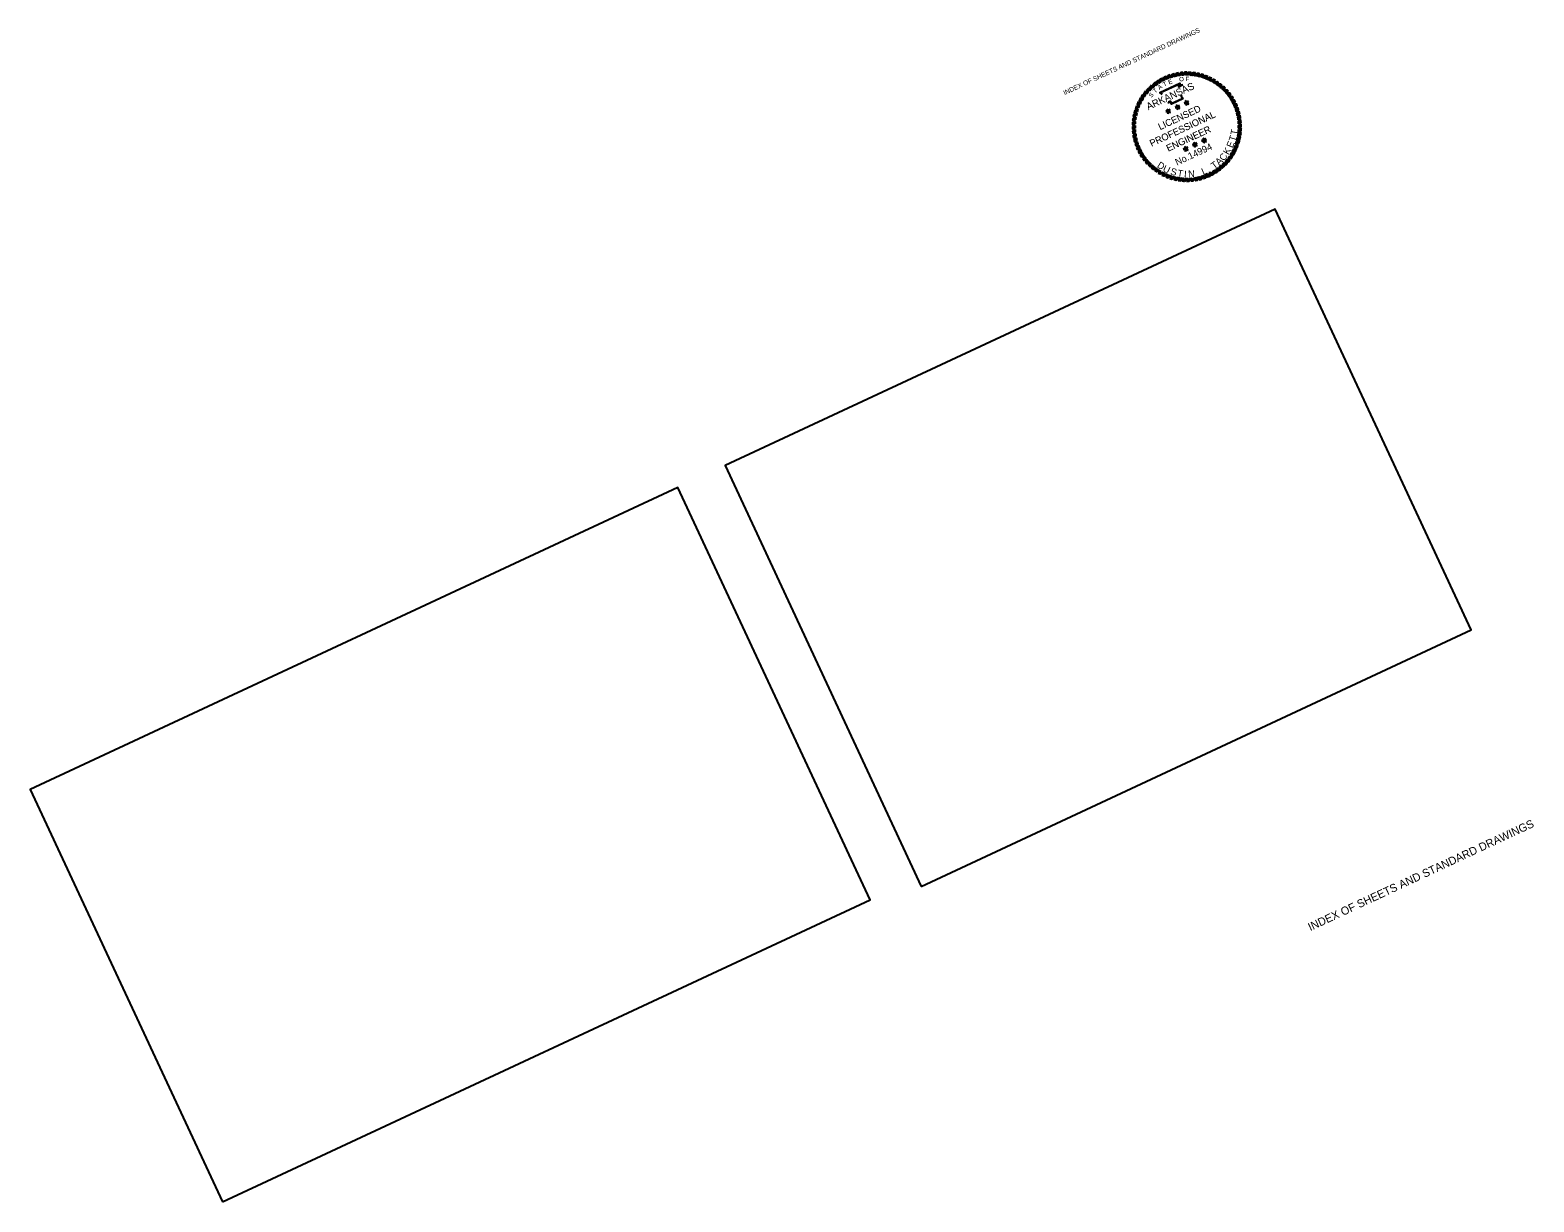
# Model space of a CAD drawing. Extents: x -22487163 to -22480035, y -237910427 to -237906052.
# Drawn here: x -22487163 to -22483810, y -237910427 to -237907814 of the extents above; entities that cross this region are included whole.
import ezdxf

# ---------------------------------------------------------------- set-up
doc = ezdxf.new("R2010")
doc.units = 0
for name, color, linetype in [('53', 7, 'Continuous'), ('54', 7, 'Continuous'), ('Default', 7, 'Continuous')]:
    doc.layers.add(name, color=color, linetype=linetype)

# ---------------------------------------------------------------- blocks, each defined once
blk = doc.blocks.new('STAR')
at = {"layer": 'Default'}
for p, q in [((0.059, 0.019), (-0.059, 0.019)), ((-0.059, 0.019), (0.036, -0.05)), ((0, 0.062), (-0.037, -0.05)), ((-0.036, -0.05), (0.059, 0.019)), ((-0.008, 0), (0.009, 0)), ((0.036, -0.05), (0, 0.062)), ((0, 0.006), (0, -0.008))]:
    blk.add_line(p, q, dxfattribs=at)
blk = doc.blocks.new('RP')
at = {"layer": 'Default'}
for p, q in [((-0.078, 1.266), (0.003, 1.33)), ((-0.058, 1.267), (0.022, 1.33)), ((-0.038, 1.267), (0.04, 1.329)), ((-0.018, 1.268), (0.059, 1.329))]:
    blk.add_line(p, q, dxfattribs=at)
for radius, start, end in [(1.268, 90.7933, 93.5307), (1.33, 87.4562, 89.8699)]:
    blk.add_arc((0, 0), radius, start, end, dxfattribs=at)

msp = doc.modelspace()

# ---------------------------------------------------------------- linework, layer by layer
at = {"layer": '54'}
for points in [[(-22485175.9, -237909723.4), (-22483949.6, -237909151.5), (-22484387.2, -237908213.1), (-22485613.5, -237908784.9)], [(-22486734.3, -237910427), (-22485289.7, -237909753.4), (-22485718.4, -237908833.9), (-22487163, -237909507.5)]]:
    msp.add_lwpolyline(points, close=True, dxfattribs=at)
at = {"layer": 'Default'}
for points in [[(-22484638.7, -237907957.7), (-22484643.9, -237907953.3), (-22484599.4, -237907932.6), (-22484601, -237907939), (-22484598, -237907937.5), (-22484595.5, -237907936.3), (-22484592.8, -237907935.4)], [(-22484638.6, -237907957.6), (-22484643.8, -237907953.2), (-22484599.3, -237907932.6), (-22484600.8, -237907939), (-22484597.8, -237907937.6), (-22484595.3, -237907936.4), (-22484592.7, -237907935.5)], [(-22484638.2, -237907957.1), (-22484642.4, -237907953.5), (-22484600.6, -237907934), (-22484602.1, -237907940.4), (-22484597.6, -237907938.2), (-22484595.2, -237907937), (-22484592.6, -237907936.2)], [(-22484638.1, -237907957), (-22484642.3, -237907953.4), (-22484600.4, -237907934), (-22484602, -237907940.4), (-22484597.5, -237907938.3), (-22484595, -237907937.1), (-22484592.4, -237907936.2)], [(-22484595.1, -237907960.1), (-22484595.5, -237907961.1), (-22484595.4, -237907962.2), (-22484594.6, -237907964.6), (-22484593.1, -237907967.7), (-22484618, -237907979.1), (-22484619.9, -237907975), (-22484620.3, -237907974.1), (-22484621.5, -237907974.2), (-22484625, -237907975.9), (-22484626.1, -237907975.2)], [(-22484595.1, -237907960.1), (-22484595.6, -237907961), (-22484595.4, -237907962.1), (-22484594.6, -237907964.5), (-22484593.2, -237907967.6), (-22484618, -237907979.1), (-22484619.9, -237907975), (-22484620.4, -237907974.1), (-22484621.5, -237907974.2), (-22484625, -237907975.9), (-22484626.1, -237907975.2)], [(-22484595.8, -237907959.7), (-22484596.4, -237907960.9), (-22484596.2, -237907962.3), (-22484595.3, -237907964.8), (-22484594.2, -237907967.2), (-22484617.6, -237907978.1), (-22484619.2, -237907974.7), (-22484619.9, -237907973.2), (-22484621.7, -237907973.5), (-22484625, -237907975), (-22484625.7, -237907974.6)], [(-22484595.8, -237907959.8), (-22484596.4, -237907961), (-22484596.1, -237907962.3), (-22484595.3, -237907964.9), (-22484594.2, -237907967.3), (-22484617.6, -237907978.1), (-22484619.2, -237907974.7), (-22484619.9, -237907973.2), (-22484621.7, -237907973.5), (-22484625, -237907975), (-22484625.7, -237907974.5)]]:
    msp.add_lwpolyline(points, dxfattribs=at)

# ---------------------------------------------------------------- block references
for name, p, xscale, yscale, rotation in [('RP', (-22484583.8, -237908029.4), 91.17655343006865, 91.17655343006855, 34.000000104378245), ('RP', (-22484583.9, -237908029.6), 91.17655343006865, 91.17655343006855, 33.804199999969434), ('RP', (-22484583.8, -237908029.4), 91.17655343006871, 91.17655343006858, 29.500000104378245), ('RP', (-22484583.9, -237908029.6), 91.17655343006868, 91.17655343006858, 29.30419999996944), ('RP', (-22484583.8, -237908029.4), 91.17655343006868, 91.17655343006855, 25.00000010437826), ('RP', (-22484583.9, -237908029.6), 91.17655343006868, 91.17655343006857, 24.804199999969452), ('RP', (-22484583.8, -237908029.4), 91.1765534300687, 91.17655343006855, 20.50000010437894), ('RP', (-22484583.9, -237908029.6), 91.17655343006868, 91.17655343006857, 20.304199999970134), ('RP', (-22484583.8, -237908029.4), 91.1765534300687, 91.17655343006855, 16.00000010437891), ('RP', (-22484583.9, -237908029.6), 91.1765534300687, 91.17655343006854, 15.804199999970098), ('RP', (-22484583.8, -237908029.4), 91.17655343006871, 91.17655343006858, 11.500000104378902), ('RP', (-22484583.9, -237908029.6), 91.17655343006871, 91.1765534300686, 11.304199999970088), ('RP', (-22484583.8, -237908029.4), 91.17655343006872, 91.17655343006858, 7.000000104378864), ('RP', (-22484583.9, -237908029.6), 91.1765534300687, 91.17655343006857, 6.804199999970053), ('RP', (-22484583.8, -237908029.4), 91.17655343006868, 91.17655343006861, 2.500000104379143), ('RP', (-22484583.9, -237908029.6), 91.17655343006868, 91.17655343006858, 2.30419999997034), ('RP', (-22484583.8, -237908029.4), 91.17655343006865, 91.17655343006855, -1.999999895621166), ('RP', (-22484583.9, -237908029.6), 91.17655343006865, 91.17655343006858, -2.19580000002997), ('RP', (-22484583.8, -237908029.4), 91.1765534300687, 91.17655343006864, -6.499999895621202), ('RP', (-22484583.9, -237908029.6), 91.17655343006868, 91.17655343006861, -6.695800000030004), ('RP', (-22484583.8, -237908029.4), 91.17655343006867, 91.17655343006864, -10.99999989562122), ('RP', (-22484583.9, -237908029.6), 91.17655343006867, 91.17655343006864, -11.195800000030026), ('RP', (-22484583.8, -237908029.4), 91.17655343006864, 91.1765534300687, -15.499999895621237), ('RP', (-22484583.9, -237908029.6), 91.17655343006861, 91.17655343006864, -15.695800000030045), ('RP', (-22484583.8, -237908029.4), 91.17655343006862, 91.17655343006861, -19.99999989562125), ('RP', (-22484583.9, -237908029.6), 91.17655343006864, 91.1765534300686, -20.195800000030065), ('RP', (-22484583.8, -237908029.4), 91.1765534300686, 91.17655343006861, -24.499999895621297), ('RP', (-22484583.9, -237908029.6), 91.1765534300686, 91.17655343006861, -24.695800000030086), ('RP', (-22484583.8, -237908029.4), 91.17655343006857, 91.17655343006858, -28.999999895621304), ('RP', (-22484583.9, -237908029.6), 91.17655343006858, 91.17655343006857, -29.19580000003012), ('RP', (-22484583.8, -237908029.4), 91.17655343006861, 91.17655343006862, -33.49999989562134), ('RP', (-22484583.9, -237908029.6), 91.17655343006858, 91.17655343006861, -33.69580000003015), ('RP', (-22484583.9, -237908029.6), 91.17655343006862, 91.17655343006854, 56.304199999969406), ('RP', (-22484583.8, -237908029.4), 91.17655343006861, 91.17655343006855, 56.500000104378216), ('RP', (-22484583.8, -237908029.4), 91.17655343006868, 91.17655343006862, 52.000000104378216), ('RP', (-22484583.9, -237908029.6), 91.17655343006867, 91.17655343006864, 51.8041999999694), ('RP', (-22484583.8, -237908029.4), 91.17655343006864, 91.1765534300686, 47.500000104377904), ('RP', (-22484583.9, -237908029.6), 91.17655343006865, 91.17655343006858, 47.30419999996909), ('RP', (-22484583.8, -237908029.4), 91.17655343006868, 91.17655343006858, 43.00000010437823), ('RP', (-22484583.9, -237908029.6), 91.17655343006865, 91.17655343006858, 42.80419999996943), ('RP', (-22484583.8, -237908029.4), 91.17655343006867, 91.17655343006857, 38.50000010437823), ('RP', (-22484583.9, -237908029.6), 91.17655343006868, 91.17655343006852, 38.304199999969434), ('RP', (-22484583.8, -237908029.4), 91.17655343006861, 91.17655343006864, -37.99999989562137), ('RP', (-22484583.9, -237908029.6), 91.17655343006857, 91.17655343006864, -38.19580000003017), ('RP', (-22484583.8, -237908029.4), 91.1765534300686, 91.17655343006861, -42.49999989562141), ('RP', (-22484583.9, -237908029.6), 91.1765534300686, 91.17655343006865, -42.69580000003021), ('RP', (-22484583.8, -237908029.4), 91.17655343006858, 91.17655343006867, -46.99999989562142), ('RP', (-22484583.9, -237908029.6), 91.17655343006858, 91.17655343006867, -47.19580000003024), ('RP', (-22484583.8, -237908029.4), 91.17655343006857, 91.1765534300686, -51.49999989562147), ('RP', (-22484583.9, -237908029.6), 91.1765534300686, 91.17655343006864, -51.69580000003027), ('RP', (-22484583.8, -237908029.4), 91.17655343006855, 91.17655343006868, -55.999999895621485), ('RP', (-22484583.9, -237908029.6), 91.17655343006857, 91.17655343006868, -56.195800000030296), ('RP', (-22484583.9, -237908029.6), 91.17655343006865, 91.17655343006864, 74.30419999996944), ('RP', (-22484583.8, -237908029.4), 91.17655343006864, 91.17655343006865, 74.50000010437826), ('RP', (-22484583.9, -237908029.6), 91.17655343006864, 91.17655343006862, 69.80419999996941), ('RP', (-22484583.8, -237908029.4), 91.17655343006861, 91.17655343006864, 70.0000001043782), ('RP', (-22484583.9, -237908029.6), 91.17655343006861, 91.1765534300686, 65.30419999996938), ('RP', (-22484583.8, -237908029.4), 91.17655343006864, 91.17655343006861, 65.50000010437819), ('RP', (-22484583.9, -237908029.6), 91.17655343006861, 91.17655343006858, 60.80419999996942), ('RP', (-22484583.8, -237908029.4), 91.17655343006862, 91.17655343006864, 61.000000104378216), ('STAR', (-22484625, -237907995.2), 91.17655343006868, 91.17655343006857, 24.804199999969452), ('STAR', (-22484625, -237907995.2), 91.17655343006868, 91.17655343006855, 25.00000010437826), ('STAR', (-22484604.5, -237907985.7), 91.17655343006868, 91.17655343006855, 25.00000010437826), ('STAR', (-22484604.5, -237907985.8), 91.17655343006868, 91.17655343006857, 24.804199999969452), ('STAR', (-22484584.1, -237907976.2), 91.17655343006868, 91.17655343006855, 25.00000010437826), ('STAR', (-22484584.1, -237907976.3), 91.17655343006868, 91.17655343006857, 24.804199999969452), ('RP', (-22484583.8, -237908029.4), 91.17655343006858, 91.17655343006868, -60.49999989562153), ('RP', (-22484583.9, -237908029.6), 91.17655343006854, 91.17655343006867, -60.69580000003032), ('RP', (-22484583.8, -237908029.4), 91.17655343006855, 91.1765534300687, -64.99999989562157), ('RP', (-22484583.9, -237908029.6), 91.17655343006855, 91.1765534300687, -65.19580000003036), ('RP', (-22484583.8, -237908029.4), 91.1765534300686, 91.17655343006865, -69.49999989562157), ('RP', (-22484583.9, -237908029.6), 91.17655343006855, 91.17655343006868, -69.69580000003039), ('RP', (-22484583.8, -237908029.4), 91.17655343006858, 91.17655343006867, -73.9999998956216), ('RP', (-22484583.9, -237908029.6), 91.17655343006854, 91.17655343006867, -74.19580000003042), ('RP', (-22484583.9, -237908029.6), 91.17655343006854, 91.17655343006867, 87.80419999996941), ('RP', (-22484583.9, -237908029.6), 91.17655343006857, 91.17655343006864, 83.30419999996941), ('RP', (-22484583.8, -237908029.4), 91.1765534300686, 91.17655343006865, 88.00000010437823), ('RP', (-22484583.8, -237908029.4), 91.17655343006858, 91.17655343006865, 83.50000010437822), ('RP', (-22484583.9, -237908029.6), 91.17655343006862, 91.17655343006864, 78.80419999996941), ('RP', (-22484583.8, -237908029.4), 91.17655343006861, 91.17655343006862, 79.00000010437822), ('RP', (-22484583.9, -237908029.6), 91.17655343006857, 91.17655343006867, -78.69580000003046), ('RP', (-22484583.8, -237908029.4), 91.17655343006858, 91.17655343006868, -78.49999989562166), ('RP', (-22484583.9, -237908029.6), 91.17655343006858, 91.17655343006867, -83.19580000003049), ('RP', (-22484583.8, -237908029.4), 91.17655343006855, 91.17655343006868, -82.99999989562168), ('RP', (-22484583.9, -237908029.6), 91.17655343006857, 91.1765534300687, -87.69580000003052), ('RP', (-22484583.8, -237908029.4), 91.17655343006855, 91.17655343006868, -87.49999989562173), ('RP', (-22484583.8, -237908029.4), 91.17655343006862, 91.17655343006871, -91.99999989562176), ('RP', (-22484583.9, -237908029.6), 91.17655343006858, 91.17655343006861, 92.3041999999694), ('RP', (-22484583.8, -237908029.4), 91.1765534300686, 91.17655343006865, 92.50000010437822), ('RP', (-22484583.9, -237908029.6), 91.17655343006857, 91.17655343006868, 96.80419999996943), ('RP', (-22484583.8, -237908029.4), 91.17655343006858, 91.17655343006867, 97.00000010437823), ('RP', (-22484583.9, -237908029.6), 91.17655343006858, 91.17655343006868, 101.30419999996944), ('RP', (-22484583.8, -237908029.4), 91.17655343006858, 91.17655343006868, 101.50000010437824), ('RP', (-22484583.9, -237908029.6), 91.17655343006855, 91.17655343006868, 105.80419999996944), ('RP', (-22484583.8, -237908029.4), 91.17655343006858, 91.17655343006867, 106.00000010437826), ('STAR', (-22484545.3, -237908060.2), 91.17655343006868, 91.17655343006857, 24.804199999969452), ('STAR', (-22484545, -237908060), 91.17655343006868, 91.17655343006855, 25.00000010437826), ('RP', (-22484583.9, -237908029.6), 91.17655343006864, 91.17655343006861, -105.69580000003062), ('RP', (-22484583.8, -237908029.4), 91.17655343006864, 91.17655343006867, -105.49999989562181), ('RP', (-22484583.9, -237908029.6), 91.17655343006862, 91.17655343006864, -101.19580000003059), ('RP', (-22484583.8, -237908029.4), 91.17655343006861, 91.17655343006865, -100.99999989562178), ('RP', (-22484583.9, -237908029.6), 91.17655343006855, 91.17655343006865, -96.69580000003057), ('RP', (-22484583.8, -237908029.4), 91.17655343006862, 91.17655343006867, -96.49999989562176), ('RP', (-22484583.9, -237908029.6), 91.17655343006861, 91.1765534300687, -92.19580000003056), ('RP', (-22484583.9, -237908029.6), 91.17655343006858, 91.17655343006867, 110.30419999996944), ('RP', (-22484583.8, -237908029.4), 91.17655343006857, 91.1765534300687, 110.50000010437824), ('RP', (-22484583.9, -237908029.6), 91.17655343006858, 91.17655343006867, 114.80419999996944), ('RP', (-22484583.8, -237908029.4), 91.1765534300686, 91.17655343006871, 115.00000010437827), ('RP', (-22484583.9, -237908029.6), 91.17655343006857, 91.1765534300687, 119.30419999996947), ('RP', (-22484583.8, -237908029.4), 91.1765534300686, 91.17655343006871, 119.50000010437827), ('RP', (-22484583.9, -237908029.6), 91.17655343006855, 91.17655343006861, 123.80419999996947), ('RP', (-22484583.8, -237908029.4), 91.17655343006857, 91.17655343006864, 124.0000001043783), ('STAR', (-22484586.2, -237908079.2), 91.17655343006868, 91.17655343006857, 24.804199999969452), ('STAR', (-22484585.9, -237908079.1), 91.17655343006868, 91.17655343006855, 25.00000010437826), ('STAR', (-22484565.7, -237908069.7), 91.17655343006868, 91.17655343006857, 24.804199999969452), ('STAR', (-22484565.4, -237908069.5), 91.17655343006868, 91.17655343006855, 25.00000010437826), ('RP', (-22484583.9, -237908029.6), 91.17655343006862, 91.17655343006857, -123.6958000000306), ('RP', (-22484583.8, -237908029.4), 91.17655343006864, 91.17655343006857, -123.49999989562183), ('RP', (-22484583.9, -237908029.6), 91.17655343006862, 91.17655343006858, -119.1958000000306), ('RP', (-22484583.8, -237908029.4), 91.17655343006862, 91.17655343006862, -118.99999989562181), ('RP', (-22484583.9, -237908029.6), 91.17655343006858, 91.17655343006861, -114.69580000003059), ('RP', (-22484583.8, -237908029.4), 91.17655343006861, 91.17655343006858, -114.49999989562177), ('RP', (-22484583.9, -237908029.6), 91.17655343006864, 91.17655343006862, -110.1958000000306), ('RP', (-22484583.8, -237908029.4), 91.17655343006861, 91.17655343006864, -109.99999989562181), ('RP', (-22484583.9, -237908029.6), 91.17655343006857, 91.17655343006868, 128.30419999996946), ('RP', (-22484583.8, -237908029.4), 91.17655343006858, 91.17655343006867, 128.50000010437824), ('RP', (-22484583.9, -237908029.6), 91.17655343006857, 91.17655343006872, 132.80419999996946), ('RP', (-22484583.8, -237908029.4), 91.17655343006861, 91.1765534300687, 133.00000010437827), ('RP', (-22484583.9, -237908029.6), 91.17655343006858, 91.17655343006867, 137.30419999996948), ('RP', (-22484583.8, -237908029.4), 91.17655343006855, 91.17655343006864, 137.5000001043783), ('RP', (-22484583.9, -237908029.6), 91.17655343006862, 91.17655343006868, 141.80419999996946), ('RP', (-22484583.8, -237908029.4), 91.17655343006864, 91.17655343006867, 142.00000010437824), ('RP', (-22484583.9, -237908029.6), 91.17655343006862, 91.17655343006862, 146.30419999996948), ('RP', (-22484583.8, -237908029.4), 91.17655343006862, 91.17655343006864, 146.5000001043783), ('RP', (-22484583.9, -237908029.6), 91.17655343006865, 91.17655343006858, -150.6958000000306), ('RP', (-22484583.8, -237908029.4), 91.1765534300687, 91.17655343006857, -150.4999998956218), ('RP', (-22484583.9, -237908029.6), 91.17655343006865, 91.17655343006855, -146.19580000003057), ('RP', (-22484583.8, -237908029.4), 91.17655343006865, 91.17655343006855, -145.99999989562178), ('RP', (-22484583.9, -237908029.6), 91.17655343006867, 91.17655343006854, -141.69580000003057), ('RP', (-22484583.8, -237908029.4), 91.17655343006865, 91.17655343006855, -141.49999989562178), ('RP', (-22484583.9, -237908029.6), 91.17655343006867, 91.17655343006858, -137.19580000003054), ('RP', (-22484583.8, -237908029.4), 91.1765534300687, 91.17655343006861, -136.99999989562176), ('RP', (-22484583.9, -237908029.6), 91.17655343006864, 91.17655343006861, -132.69580000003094), ('RP', (-22484583.8, -237908029.4), 91.17655343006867, 91.1765534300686, -132.49999989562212), ('RP', (-22484583.9, -237908029.6), 91.17655343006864, 91.17655343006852, -128.19580000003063), ('RP', (-22484583.8, -237908029.4), 91.17655343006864, 91.17655343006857, -127.99999989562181), ('RP', (-22484583.9, -237908029.6), 91.17655343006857, 91.1765534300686, 150.80419999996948), ('RP', (-22484583.8, -237908029.4), 91.1765534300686, 91.17655343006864, 151.0000001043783), ('RP', (-22484583.9, -237908029.6), 91.1765534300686, 91.17655343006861, 155.30419999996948), ('RP', (-22484583.8, -237908029.4), 91.17655343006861, 91.17655343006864, 155.50000010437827), ('RP', (-22484583.9, -237908029.6), 91.17655343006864, 91.17655343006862, 159.80419999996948), ('RP', (-22484583.8, -237908029.4), 91.17655343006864, 91.17655343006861, 160.0000001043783), ('RP', (-22484583.9, -237908029.6), 91.17655343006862, 91.17655343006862, 164.30419999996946), ('RP', (-22484583.8, -237908029.4), 91.17655343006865, 91.17655343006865, 164.50000010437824), ('RP', (-22484583.9, -237908029.6), 91.17655343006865, 91.17655343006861, 168.80419999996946), ('RP', (-22484583.8, -237908029.4), 91.17655343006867, 91.1765534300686, 169.00000010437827), ('RP', (-22484583.9, -237908029.6), 91.17655343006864, 91.17655343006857, 173.30419999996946), ('RP', (-22484583.8, -237908029.4), 91.17655343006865, 91.17655343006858, 173.5000001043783), ('RP', (-22484583.9, -237908029.6), 91.17655343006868, 91.17655343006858, 177.80419999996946), ('RP', (-22484583.8, -237908029.4), 91.17655343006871, 91.17655343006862, 178.00000010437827), ('RP', (-22484583.9, -237908029.6), 91.17655343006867, 91.17655343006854, -177.6958000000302), ('RP', (-22484583.8, -237908029.4), 91.17655343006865, 91.17655343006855, -177.49999989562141), ('RP', (-22484583.9, -237908029.6), 91.17655343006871, 91.17655343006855, -173.19580000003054), ('RP', (-22484583.8, -237908029.4), 91.1765534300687, 91.1765534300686, -172.99999989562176), ('RP', (-22484583.9, -237908029.6), 91.17655343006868, 91.17655343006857, -168.69580000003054), ('RP', (-22484583.8, -237908029.4), 91.17655343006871, 91.17655343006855, -168.49999989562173), ('RP', (-22484583.9, -237908029.6), 91.17655343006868, 91.17655343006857, -164.19580000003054), ('RP', (-22484583.8, -237908029.4), 91.17655343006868, 91.17655343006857, -163.99999989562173), ('RP', (-22484583.9, -237908029.6), 91.17655343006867, 91.17655343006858, -159.69580000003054), ('RP', (-22484583.8, -237908029.4), 91.1765534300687, 91.17655343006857, -159.49999989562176), ('RP', (-22484583.9, -237908029.6), 91.17655343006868, 91.17655343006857, -155.19580000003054), ('RP', (-22484583.8, -237908029.4), 91.17655343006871, 91.1765534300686, -154.99999989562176)]:
    msp.add_blockref(name, p, dxfattribs=dict(at, xscale=xscale, yscale=yscale, rotation=rotation))

# ---------------------------------------------------------------- texts
at = {"layer": '53'}
msp.add_text('INDEX OF SHEETS AND STANDARD DRAWINGS', height=18, rotation=25, dxfattribs=at).set_placement((-22484308.5, -237909823.3))
at = {"layer": '54'}
msp.add_text('INDEX OF SHEETS AND STANDARD DRAWINGS', height=10.552, rotation=25, dxfattribs=at).set_placement((-22484856.3, -237907959.3))
at = {"layer": 'Default'}
for s, height, rotation, p in [('E', 9.67, 21.672, (-22484623.2, -237907935.6)), ('E', 9.67, 21.4762, (-22484623, -237907935.6)), ('O', 9.67, 6.2218, (-22484600.5, -237907928.7)), ('O', 9.67, 6.026, (-22484600.3, -237907928.8)), ('F', 9.67, 0.3628, (-22484586.5, -237907927.8)), ('F', 9.67, 0.167, (-22484586.4, -237907927.9)), ('ARKANSAS', 15.79, 25, (-22484669.7, -237907992.9)), ('ARKANSAS', 15.79, 24.8042, (-22484669.7, -237907992.7)), ('S', 9.67, 44.7726, (-22484663.2, -237907965.6)), ('S', 9.67, 44.5768, (-22484663.2, -237907965.4)), ('T', 9.67, 41.9015, (-22484654.4, -237907955.4)), ('T', 9.67, 41.7057, (-22484654.3, -237907955.3)), ('A', 9.67, 33.6788, (-22484645, -237907947.6)), ('A', 9.67, 33.483, (-22484644.9, -237907947.5)), ('T', 9.67, 26.4789, (-22484634.5, -237907940.6)), ('T', 9.67, 26.2831, (-22484634.4, -237907940.6)), ('LICENSED', 15.28, 24.8042, (-22484643.6, -237908037.4)), ('LICENSED', 15.28, 25, (-22484643.4, -237908037.5)), ('PROFESSIONAL', 15.285, 24.8042, (-22484662.6, -237908074.4)), ('PROFESSIONAL', 15.285, 25, (-22484662.3, -237908074.5)), ('ENGINEER', 15.28, 24.8042, (-22484625.5, -237908085.4)), ('ENGINEER', 15.28, 25, (-22484625.1, -237908085.4)), ('T', 15.3, 73.0746, (-22484476.1, -237908063.7)), ('T', 15.3, 79.3036, (-22484471.8, -237908049.2)), ('No.14994', 15.22, 25, (-22484605.7, -237908116.5)), ('C', 15.3, 58.6577, (-22484500, -237908107.1)), ('K', 15.3, 60.1218, (-22484491, -237908093.3)), ('E', 15.3, 67.4392, (-22484482.1, -237908077.9)), ('D', 15.3, 327.9045, (-22484651.6, -237908119.1)), ('U', 15.3, 334.8131, (-22484638.8, -237908128.1)), ('S', 15.3, 345.368, (-22484621.6, -237908135.9)), ('T', 15.3, 350.101, (-22484606, -237908140.1)), ('N', 15.3, 2.2539, (-22484580.7, -237908142.3)), ('L', 15.3, 23.474, (-22484547.3, -237908137.6)), ('T', 15.3, 36.7303, (-22484522.9, -237908124.9)), ('A', 15.3, 44.3817, (-22484511.8, -237908116.5)), ('I', 15.3, 355.8687, (-22484590.5, -237908142.3)), ('.', 15.3, 29.1489, (-22484535.6, -237908133))]:
    msp.add_text(s, height=height, rotation=rotation, dxfattribs=at).set_placement(p)

doc.saveas('drawing.dxf')
